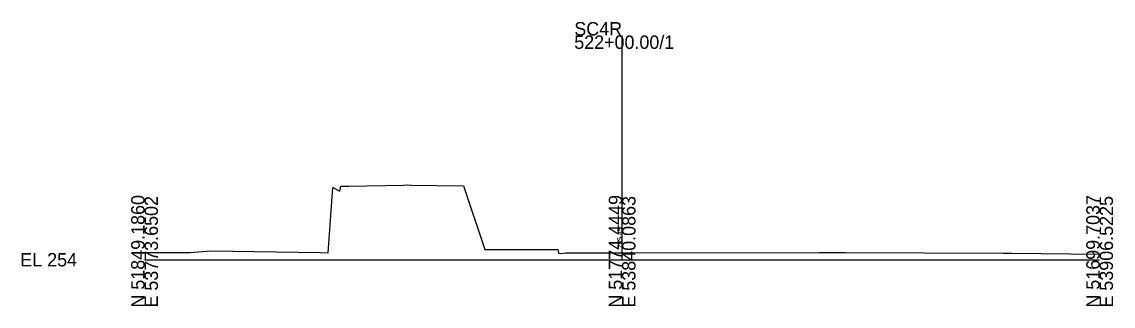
# Model space of a CAD drawing. Extents: x 8330 to 11559, y 6854 to 26418.
# Drawn here: x 9330.1 to 9558.7, y 20854.5 to 20913.9 of the extents above; entities that cross this region are included whole.
import ezdxf

# ---------------------------------------------------------------- set-up
doc = ezdxf.new("R2010")
doc.units = 0
for name, color, linetype in [('Level 10', 7, 'Continuous'), ('Level 60', 7, 'Continuous'), ('Level 63', 7, 'Continuous')]:
    doc.layers.add(name, color=color, linetype=linetype)

msp = doc.modelspace()

# ---------------------------------------------------------------- linework, layer by layer
at = {"layer": 'Level 60'}
for p, q in [((9394.31, 20865.65), (9395.23, 20879.28)), ((9395.23, 20879.28), (9396.75, 20878.51)), ((9396.75, 20878.51), (9396.91, 20879.54)), ((9396.91, 20879.54), (9398.58, 20879.56)), ((9398.58, 20879.56), (9409.98, 20879.78)), ((9409.98, 20879.78), (9410.84, 20879.79)), ((9410.84, 20879.79), (9411.67, 20879.78)), ((9411.67, 20879.78), (9422.64, 20879.6)), ((9422.64, 20879.6), (9427.08, 20866.32)), ((9355.83, 20865.71), (9360.99, 20865.71)), ((9360.99, 20865.71), (9365.28, 20865.71)), ((9365.28, 20865.71), (9369.68, 20866.06)), ((9369.68, 20866.06), (9392.61, 20865.69)), ((9392.61, 20865.69), (9394.31, 20865.65)), ((9427.08, 20866.32), (9442.34, 20866.29)), ((9442.34, 20866.29), (9442.48, 20865.54)), ((9442.48, 20865.54), (9443.18, 20865.51)), ((9443.18, 20865.51), (9443.97, 20865.6)), ((9443.97, 20865.6), (9455.83, 20865.62)), ((9455.83, 20865.62), (9497.14, 20865.68)), ((9497.14, 20865.68), (9502.63, 20865.67)), ((9502.63, 20865.67), (9535.66, 20865.57)), ((9535.66, 20865.57), (9537.44, 20865.56)), ((9537.44, 20865.56), (9555.83, 20865.33))]:
    msp.add_line(p, q, dxfattribs=at)
at = {"layer": 'Level 63'}
for p, q in [((9455.83, 20864.17), (9455.83, 20911.03)), ((9355.83, 20864.17), (9455.83, 20864.17)), ((9455.83, 20864.17), (9555.83, 20864.17))]:
    msp.add_line(p, q, dxfattribs=at)

# ---------------------------------------------------------------- texts
at = {"layer": 'Level 10'}
msp.add_text('255.45', height=1, rotation=90, dxfattribs=at).set_placement((9455.83, 20866.62))
at = {"layer": 'Level 63'}
for s, p in [('SC4R', (9445.83, 20911.03)), ('522+00.00/1', (9445.82, 20908.23)), ('EL 254', (9329.82, 20862.77))]:
    msp.add_text(s, height=2.8, dxfattribs=at).set_placement(p)
for s, p in [('N 51849.1860', (9355.83, 20854.17)), ('E 53773.6502', (9358.63, 20854.17)), ('N 51774.4449', (9455.83, 20854.17)), ('E 53840.0863', (9458.63, 20854.17)), ('N 51699.7037', (9555.83, 20854.17)), ('E 53906.5225', (9558.63, 20854.17))]:
    msp.add_text(s, height=2.8, rotation=90, dxfattribs=at).set_placement(p)

doc.saveas('drawing.dxf')
